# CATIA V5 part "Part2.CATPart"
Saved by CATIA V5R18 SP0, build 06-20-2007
Part number: Part2
Bounding box of the stored display mesh (mm): x -29.961 to 100, y -30 to 30, z -29.961 to 29.961
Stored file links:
  D:\Shriniwas\v5_r19\c16_CAT_v5r19\c16_Part\Sperical Joint\Part2.CATPart
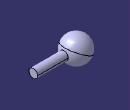
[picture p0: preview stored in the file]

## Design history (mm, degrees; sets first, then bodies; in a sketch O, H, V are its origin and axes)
Body1 (main body)
  Sketch1 on xy-plane, origin (0, 0, 0), H (1, 0, 0), V (0, 1, 0)
    arc A1 centre (0, 0) radius 30 from (0, -30) to (0, 30) ccw
    point P1 (0, 30)
    point P2 (0, -30)
    line L1 (0, -30) -> (0, 30)
    length L1 = 60
    coincidence: P1 V, P2 V
    vertical: L1 V
  Shaft1: profile Sketch1, axis Sketch1.L1, angle 360
  Sketch2 on yz-plane, origin (0, 0, 0), H (0, 1, 0), V (0, 0, 1)
    circle A1 centre (0, 0) radius 10
    radius A1 = 10
  Pad1: profile Sketch2, direction (1, 0, 0), length 100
